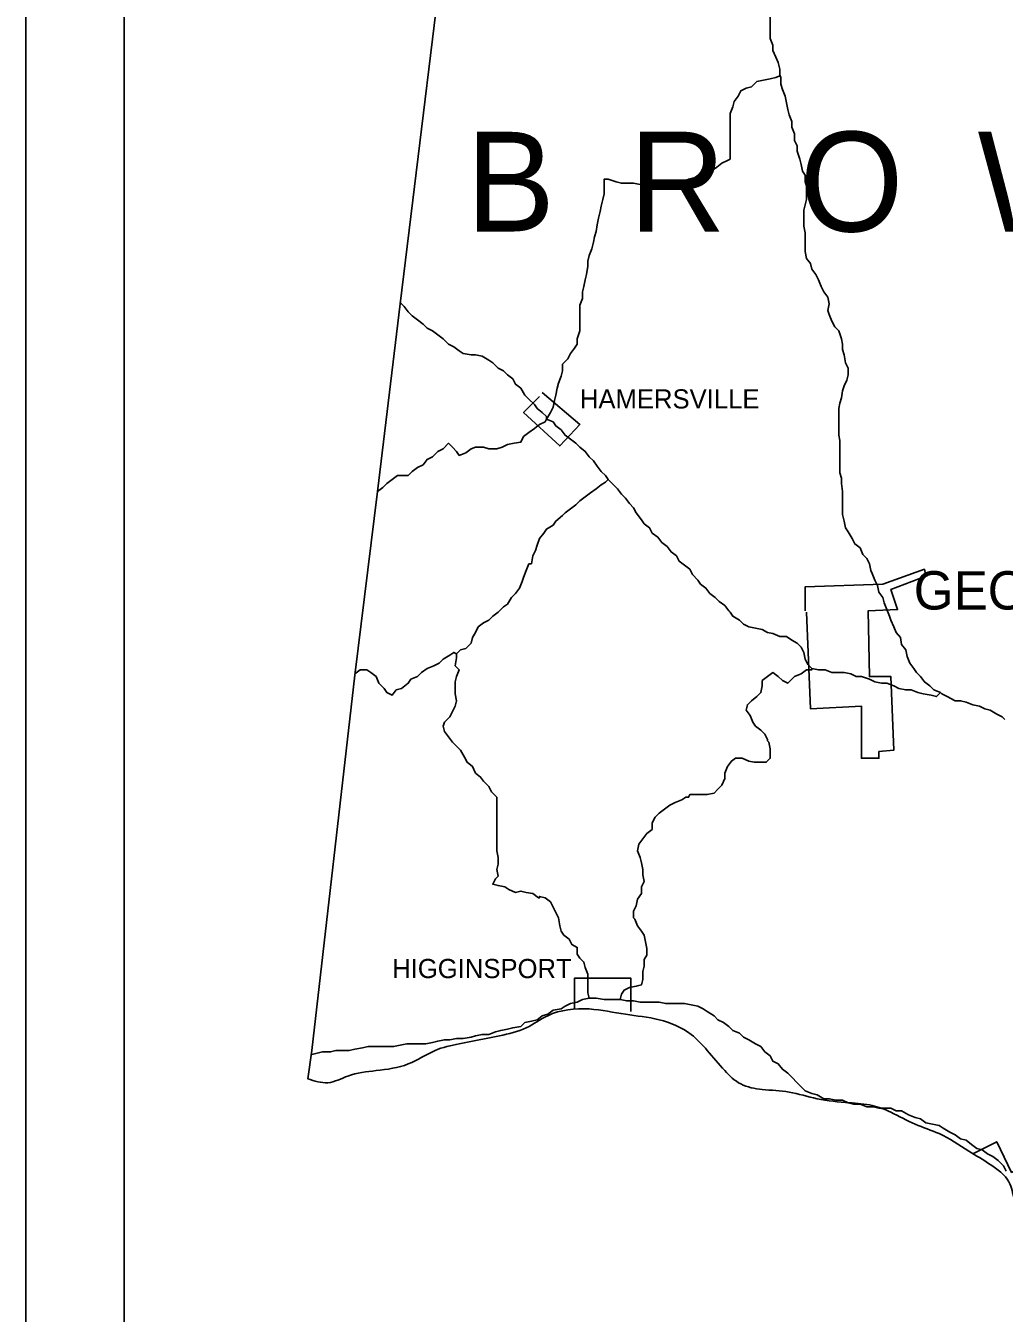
# Model space of a CAD drawing. Extents: x 0 to 40.2, y 0 to 22.
# Drawn here: x 2 to 2.995, y 16.376 to 17.685 of the extents above; entities that cross this region are included whole.
import ezdxf

# ---------------------------------------------------------------- set-up
doc = ezdxf.new("R2010")
doc.units = 0
for name, color, linetype in [('Default', 7, 'Continuous'), ('SH_Data', 7, 'Continuous'), ('TR_Turning_Path1', 7, 'Continuous')]:
    doc.layers.add(name, color=color, linetype=linetype)

msp = doc.modelspace()

# ---------------------------------------------------------------- linework, layer by layer
at = {"layer": 'Default'}
for points in [[(2.5335, 18.7973), (2.5253, 18.6677), (2.5172, 18.545), (2.5049, 18.4291), (2.4899, 18.3105), (2.4872, 18.2764), (2.4708, 18.1374), (2.4531, 17.9969), (2.4354, 17.8497), (2.3808, 17.4025), (2.3576, 17.2116), (2.3345, 17.0248), (2.2908, 16.6431), (2.2867, 16.6144)], [(2.7667, 17.6356), (2.7667, 17.6411), (2.7653, 17.6479), (2.7626, 17.6533), (2.7598, 17.6602), (2.7598, 17.6656), (2.7571, 17.6724), (2.7571, 17.6792), (2.7571, 17.6861), (2.7571, 17.6929), (2.7571, 17.6983), (2.7585, 17.7052), (2.7598, 17.7106), (2.7598, 17.7174), (2.7598, 17.7256), (2.7598, 17.7311), (2.7598, 17.7379), (2.7653, 17.7433), (2.768, 17.7488), (2.7721, 17.7542), (2.7748, 17.7597), (2.7762, 17.7665), (2.7762, 17.7665)], [(2.7162, 17.5511), (2.7162, 17.5579), (2.7162, 17.5634), (2.7162, 17.5702), (2.7162, 17.577), (2.7162, 17.5824), (2.7162, 17.5893), (2.7162, 17.5961), (2.7189, 17.6029), (2.7203, 17.6084), (2.7244, 17.6138), (2.7271, 17.6193), (2.7326, 17.622), (2.738, 17.6233), (2.7435, 17.6288), (2.7503, 17.6302), (2.7571, 17.6315), (2.7626, 17.6329), (2.7667, 17.6343), (2.7667, 17.6356)], [(2.7898, 17.5375), (2.7885, 17.5443), (2.7871, 17.5497), (2.7844, 17.5579), (2.7844, 17.5634), (2.7817, 17.5688), (2.7817, 17.5756), (2.7789, 17.5824), (2.7789, 17.5879), (2.7762, 17.5947), (2.7748, 17.6002), (2.7735, 17.607), (2.7721, 17.6138), (2.7694, 17.6206), (2.768, 17.6261), (2.768, 17.6329), (2.7667, 17.6356)], [(2.5799, 17.4761), (2.5812, 17.4829), (2.5826, 17.4897), (2.584, 17.4966), (2.5853, 17.502), (2.5867, 17.5088), (2.5881, 17.5143), (2.5881, 17.5211), (2.5881, 17.5293), (2.5921, 17.5293), (2.6003, 17.5265), (2.6058, 17.5252), (2.6112, 17.5252), (2.6181, 17.5252), (2.6249, 17.5238), (2.6317, 17.5225), (2.6371, 17.5225), (2.644, 17.5225), (2.6508, 17.5211), (2.6562, 17.5197), (2.6617, 17.5225), (2.6685, 17.5252), (2.674, 17.5293), (2.6794, 17.5306), (2.6862, 17.532), (2.6917, 17.5334), (2.6971, 17.5375), (2.7026, 17.5415), (2.708, 17.5456), (2.7135, 17.5484), (2.7162, 17.5497), (2.7162, 17.5511)], [(2.7912, 17.4843), (2.7912, 17.4897), (2.7912, 17.4979), (2.7926, 17.5034), (2.7939, 17.5088), (2.7939, 17.5143), (2.7939, 17.5225), (2.7926, 17.5265), (2.7926, 17.5334), (2.7898, 17.5375)], [(2.8362, 17.3316), (2.8362, 17.337), (2.8335, 17.3425), (2.8321, 17.3507), (2.8307, 17.3561), (2.8307, 17.3616), (2.8294, 17.367), (2.8267, 17.3752), (2.8226, 17.3793), (2.8198, 17.3848), (2.8171, 17.3916), (2.8157, 17.3957), (2.8171, 17.4025), (2.8157, 17.4093), (2.8117, 17.4147), (2.8089, 17.4202), (2.8062, 17.427), (2.8035, 17.4325), (2.7994, 17.4379), (2.798, 17.4434), (2.7939, 17.4488), (2.7926, 17.4556), (2.7926, 17.4625), (2.7926, 17.4679), (2.7926, 17.4747), (2.7912, 17.4816), (2.7912, 17.4843), (2.7912, 17.4843)], [(2.5294, 17.2852), (2.5335, 17.292), (2.5362, 17.2975), (2.5376, 17.3043), (2.539, 17.3098), (2.5403, 17.3166), (2.5417, 17.322), (2.5444, 17.3289), (2.5458, 17.3343), (2.5458, 17.3411), (2.5512, 17.3466), (2.554, 17.352), (2.5581, 17.3575), (2.5608, 17.3616), (2.5608, 17.367), (2.5635, 17.3752), (2.5635, 17.382), (2.5635, 17.3875), (2.5635, 17.3943), (2.5635, 17.4011), (2.5662, 17.4079), (2.5662, 17.4147), (2.5676, 17.4202), (2.569, 17.427), (2.5703, 17.4325), (2.5717, 17.4407), (2.5717, 17.4461), (2.5731, 17.4516), (2.5758, 17.4584), (2.5772, 17.4652), (2.5785, 17.4706), (2.5799, 17.4761), (2.5799, 17.4761)], [(2.3808, 17.4038), (2.3849, 17.3997), (2.389, 17.3943), (2.3931, 17.3902), (2.3985, 17.3861), (2.404, 17.382), (2.4081, 17.3779), (2.4135, 17.3752), (2.419, 17.3711), (2.4244, 17.367), (2.4299, 17.3616), (2.4354, 17.3588), (2.4408, 17.3548), (2.4449, 17.352), (2.4531, 17.3507), (2.4572, 17.3507), (2.464, 17.3493), (2.4708, 17.3452), (2.4749, 17.3425), (2.4803, 17.337), (2.4858, 17.3343), (2.4899, 17.3302), (2.4953, 17.3261), (2.4981, 17.3207), (2.5035, 17.3166), (2.5076, 17.3098), (2.5117, 17.3057), (2.5172, 17.3002), (2.5199, 17.2961), (2.5253, 17.292), (2.5294, 17.2879), (2.5294, 17.2852)], [(2.3808, 17.4038), (2.3849, 17.3997), (2.389, 17.3943), (2.3931, 17.3902), (2.3985, 17.3861), (2.404, 17.382), (2.4081, 17.3779), (2.4135, 17.3752), (2.419, 17.3711), (2.4244, 17.367), (2.4299, 17.3616), (2.4354, 17.3588), (2.4408, 17.3548), (2.4449, 17.352), (2.4531, 17.3507), (2.4572, 17.3507), (2.464, 17.3493), (2.4708, 17.3452), (2.4749, 17.3425), (2.4803, 17.337), (2.4858, 17.3343), (2.4899, 17.3302), (2.4953, 17.3261), (2.4981, 17.3207), (2.5035, 17.3166), (2.5076, 17.3098), (2.5117, 17.3057), (2.5172, 17.3002), (2.5199, 17.2961), (2.5253, 17.292), (2.5294, 17.2879), (2.5294, 17.2852)], [(2.828, 17.2498), (2.828, 17.2552), (2.828, 17.2634), (2.8267, 17.2689), (2.8267, 17.2757), (2.8267, 17.2825), (2.8267, 17.2879), (2.8267, 17.2961), (2.828, 17.3016), (2.8294, 17.307), (2.8307, 17.3139), (2.8321, 17.3193), (2.8348, 17.3248), (2.8362, 17.3302), (2.8362, 17.3316)], [(2.5226, 17.3084), (2.5063, 17.292), (2.5431, 17.258), (2.5635, 17.2798), (2.5253, 17.3125)], [(2.4408, 17.2484), (2.4476, 17.2511), (2.4531, 17.2552), (2.4572, 17.2566), (2.4654, 17.2566), (2.4708, 17.2552), (2.479, 17.2552), (2.4844, 17.2566), (2.4899, 17.2593), (2.4967, 17.2607), (2.5035, 17.262), (2.5063, 17.2675), (2.5117, 17.2716), (2.5172, 17.2757), (2.5226, 17.2798), (2.5281, 17.2825), (2.5294, 17.2852), (2.5294, 17.2852)], [(2.5294, 17.2852), (2.5362, 17.2825), (2.539, 17.2784), (2.5444, 17.2743), (2.5485, 17.2689), (2.554, 17.2648), (2.5594, 17.2607), (2.5635, 17.2566), (2.569, 17.2525), (2.5731, 17.247), (2.5772, 17.243), (2.5812, 17.2375), (2.5853, 17.232), (2.5894, 17.228), (2.5921, 17.2239)], [(2.5294, 17.2852), (2.5362, 17.2825), (2.539, 17.2784), (2.5444, 17.2743), (2.5485, 17.2689), (2.554, 17.2648), (2.5594, 17.2607), (2.5635, 17.2566), (2.569, 17.2525), (2.5731, 17.247), (2.5772, 17.243), (2.5812, 17.2375), (2.5853, 17.232), (2.5894, 17.228), (2.5921, 17.2239)], [(2.3576, 17.2116), (2.3631, 17.2157), (2.3672, 17.2198), (2.3726, 17.2239), (2.3781, 17.228), (2.3835, 17.228), (2.389, 17.228), (2.3931, 17.232), (2.3985, 17.2361), (2.404, 17.2389), (2.4081, 17.2443), (2.4135, 17.247), (2.419, 17.2525), (2.4244, 17.2552), (2.4299, 17.2607), (2.434, 17.2566), (2.4381, 17.2525), (2.4408, 17.2484), (2.4408, 17.2484)], [(2.8307, 17.1993), (2.8307, 17.2061), (2.8307, 17.2116), (2.8294, 17.2198), (2.8294, 17.2252), (2.828, 17.2307), (2.828, 17.2375), (2.828, 17.2443), (2.828, 17.2498)], [(2.5144, 17.138), (2.5158, 17.1462), (2.5185, 17.1516), (2.5199, 17.1571), (2.5226, 17.1639), (2.5267, 17.1693), (2.5294, 17.1734), (2.5362, 17.1775), (2.539, 17.1816), (2.5458, 17.1871), (2.5485, 17.1898), (2.554, 17.1939), (2.5594, 17.198), (2.5635, 17.2021), (2.569, 17.2061), (2.5744, 17.2102), (2.5799, 17.2143), (2.5853, 17.2184), (2.5894, 17.2211), (2.5921, 17.2239)], [(2.5921, 17.2239), (2.5962, 17.2198), (2.6017, 17.2143), (2.6058, 17.2089), (2.6099, 17.2048), (2.614, 17.1993), (2.6181, 17.1952), (2.6208, 17.1898), (2.6262, 17.183), (2.629, 17.1789), (2.6344, 17.1748), (2.6371, 17.1693), (2.6426, 17.1652), (2.6467, 17.1598), (2.6521, 17.1557), (2.6562, 17.1502), (2.6617, 17.1462), (2.6644, 17.1407), (2.6699, 17.1366), (2.6753, 17.1325), (2.678, 17.1271), (2.6835, 17.1216), (2.6862, 17.1175), (2.6917, 17.1134), (2.6958, 17.108), (2.7012, 17.1039), (2.7053, 17.0998), (2.7108, 17.0957), (2.7149, 17.0903), (2.7162, 17.0889)], [(2.5921, 17.2239), (2.5962, 17.2198), (2.6017, 17.2143), (2.6058, 17.2089), (2.6099, 17.2048), (2.614, 17.1993), (2.6181, 17.1952), (2.6208, 17.1898), (2.6262, 17.183), (2.629, 17.1789), (2.6344, 17.1748), (2.6371, 17.1693), (2.6426, 17.1652), (2.6467, 17.1598), (2.6521, 17.1557), (2.6562, 17.1502), (2.6617, 17.1462), (2.6644, 17.1407), (2.6699, 17.1366), (2.6753, 17.1325), (2.678, 17.1271), (2.6835, 17.1216), (2.6862, 17.1175), (2.6917, 17.1134), (2.6958, 17.108), (2.7012, 17.1039), (2.7053, 17.0998), (2.7108, 17.0957), (2.7149, 17.0903), (2.7162, 17.0889)], [(2.8594, 17.1312), (2.858, 17.138), (2.8553, 17.1434), (2.8512, 17.1475), (2.8485, 17.1543), (2.843, 17.1584), (2.8403, 17.1639), (2.8362, 17.1707), (2.8335, 17.1748), (2.8321, 17.1816), (2.8307, 17.1884), (2.8307, 17.1939), (2.8307, 17.1993)], [(2.4381, 17.0466), (2.4422, 17.0507), (2.4476, 17.0521), (2.4531, 17.0575), (2.4544, 17.063), (2.4572, 17.0684), (2.4599, 17.0739), (2.4654, 17.078), (2.4708, 17.0807), (2.4749, 17.0848), (2.4803, 17.0889), (2.4858, 17.0943), (2.4899, 17.0971), (2.494, 17.1039), (2.4981, 17.108), (2.5022, 17.1134), (2.5049, 17.1202), (2.5063, 17.1243), (2.509, 17.1312), (2.5117, 17.138), (2.5144, 17.138)], [(2.7939, 17.0889), (2.798, 16.9907), (2.8498, 16.9934), (2.8498, 16.9403), (2.8676, 16.9403), (2.8676, 16.9471), (2.8826, 16.9485), (2.8798, 17.0234), (2.858, 17.0234), (2.8567, 17.0903), (2.8866, 17.0916), (2.8798, 17.1121), (2.9153, 17.1257), (2.9139, 17.1325), (2.8717, 17.1175), (2.7926, 17.1148), (2.7926, 17.0903)], [(2.9303, 17.0071), (2.9235, 17.0098), (2.9194, 17.0139), (2.9139, 17.018), (2.9098, 17.0234), (2.9057, 17.0275), (2.903, 17.0316), (2.8989, 17.0371), (2.8962, 17.0439), (2.8948, 17.0507), (2.8907, 17.0562), (2.8894, 17.063), (2.8853, 17.0684), (2.8826, 17.0739), (2.8798, 17.0807), (2.8785, 17.0848), (2.8757, 17.0916), (2.873, 17.0984), (2.8717, 17.1039), (2.8676, 17.1093), (2.8662, 17.1162), (2.8635, 17.1216), (2.8607, 17.1284), (2.8594, 17.1312)], [(2.7162, 17.0889), (2.7189, 17.0848), (2.7258, 17.0807), (2.7299, 17.0766), (2.7353, 17.0739), (2.7421, 17.0725), (2.7489, 17.0712), (2.7544, 17.0684), (2.7598, 17.0671), (2.7667, 17.0643), (2.7735, 17.0643), (2.7789, 17.0603), (2.7844, 17.0575), (2.7885, 17.0534), (2.7912, 17.048), (2.7926, 17.0412), (2.7953, 17.0357), (2.7994, 17.0316), (2.7994, 17.0316)], [(2.7162, 17.0889), (2.7189, 17.0848), (2.7258, 17.0807), (2.7299, 17.0766), (2.7353, 17.0739), (2.7421, 17.0725), (2.7489, 17.0712), (2.7544, 17.0684), (2.7598, 17.0671), (2.7667, 17.0643), (2.7735, 17.0643), (2.7789, 17.0603), (2.7844, 17.0575), (2.7885, 17.0534), (2.7912, 17.048), (2.7926, 17.0412), (2.7953, 17.0357), (2.7994, 17.0316), (2.7994, 17.0316)], [(2.3345, 17.0262), (2.3399, 17.0303), (2.3467, 17.0303), (2.3508, 17.0275), (2.3563, 17.0234), (2.359, 17.0166), (2.3645, 17.0112), (2.3672, 17.0071), (2.3726, 17.0044), (2.3767, 17.0098), (2.3822, 17.0112), (2.389, 17.0166), (2.3917, 17.0207), (2.3985, 17.0234), (2.4026, 17.0275), (2.4081, 17.0316), (2.4149, 17.0344), (2.4204, 17.0371), (2.4244, 17.0412), (2.4313, 17.0453), (2.4354, 17.048), (2.4381, 17.0466)], [(2.479, 16.9007), (2.4735, 16.9062), (2.4708, 16.9116), (2.4654, 16.9171), (2.4626, 16.9212), (2.4572, 16.9253), (2.4544, 16.9321), (2.449, 16.9362), (2.4463, 16.9416), (2.4422, 16.9485), (2.4381, 16.9525), (2.434, 16.9566), (2.4299, 16.9621), (2.4258, 16.9675), (2.4244, 16.973), (2.4258, 16.9771), (2.4313, 16.9825), (2.434, 16.988), (2.4367, 16.9934), (2.4381, 16.9989), (2.4367, 17.0057), (2.4367, 17.0112), (2.4367, 17.018), (2.4381, 17.0234), (2.4408, 17.0303), (2.4367, 17.0344), (2.4381, 17.0425), (2.4381, 17.0439), (2.4381, 17.0466)], [(2.7544, 16.9594), (2.7517, 16.9648), (2.7476, 16.9689), (2.7421, 16.973), (2.7394, 16.9771), (2.7367, 16.9839), (2.7326, 16.9894), (2.7339, 16.9948), (2.738, 16.9989), (2.7435, 17.003), (2.7476, 17.0071), (2.7489, 17.0139), (2.7489, 17.0194), (2.7544, 17.0234), (2.7598, 17.0275), (2.7653, 17.0234), (2.7694, 17.0194), (2.7748, 17.0166), (2.7789, 17.0207), (2.7817, 17.0234), (2.7885, 17.0262), (2.7939, 17.0303), (2.7994, 17.0303), (2.7994, 17.0316)], [(2.7994, 17.0316), (2.8062, 17.0303), (2.813, 17.0303), (2.8198, 17.0275), (2.8253, 17.0275), (2.8321, 17.0275), (2.8389, 17.0262), (2.8444, 17.0234), (2.8498, 17.0234), (2.858, 17.0207), (2.8635, 17.018), (2.8703, 17.0166), (2.8757, 17.0166), (2.8826, 17.0139), (2.888, 17.0112), (2.8948, 17.0098), (2.9003, 17.0098), (2.9071, 17.0071), (2.9126, 17.0057), (2.9207, 17.0044), (2.9262, 17.003), (2.9289, 17.0057), (2.9303, 17.0071)], [(2.7994, 17.0316), (2.8062, 17.0303), (2.813, 17.0303), (2.8198, 17.0275), (2.8253, 17.0275), (2.8321, 17.0275), (2.8389, 17.0262), (2.8444, 17.0234), (2.8498, 17.0234), (2.858, 17.0207), (2.8635, 17.018), (2.8703, 17.0166), (2.8757, 17.0166), (2.8826, 17.0139), (2.888, 17.0112), (2.8948, 17.0098), (2.9003, 17.0098), (2.9071, 17.0071), (2.9126, 17.0057), (2.9207, 17.0044), (2.9262, 17.003), (2.9289, 17.0057), (2.9303, 17.0071)], [(2.9303, 17.0071), (2.9316, 17.0057), (2.9371, 17.003), (2.9453, 16.9989), (2.9507, 16.9989), (2.9562, 16.9975), (2.963, 16.9948), (2.9698, 16.9934), (2.9753, 16.9907), (2.9807, 16.9894), (2.9875, 16.9853), (2.993, 16.9825)], [(2.9303, 17.0071), (2.9316, 17.0057), (2.9371, 17.003), (2.9453, 16.9989), (2.9507, 16.9989), (2.9562, 16.9975), (2.963, 16.9948), (2.9698, 16.9934), (2.9753, 16.9907), (2.9807, 16.9894), (2.9875, 16.9853), (2.993, 16.9825)], [(2.993, 16.9825), (2.9875, 16.9853), (2.9807, 16.9894), (2.9753, 16.9907), (2.9698, 16.9934), (2.963, 16.9948), (2.9562, 16.9975), (2.9507, 16.9989), (2.9453, 16.9989), (2.9371, 17.003), (2.9316, 17.0057), (2.9303, 17.0071)], [(2.9957, 16.9798), (2.9944, 16.9812), (2.993, 16.9825)], [(2.6753, 16.9035), (2.6808, 16.9035), (2.6862, 16.9035), (2.693, 16.9035), (2.6999, 16.9048), (2.7039, 16.9089), (2.708, 16.913), (2.7108, 16.9198), (2.7108, 16.9253), (2.7135, 16.9321), (2.7176, 16.9375), (2.7217, 16.9403), (2.7285, 16.9403), (2.7353, 16.9375), (2.7408, 16.9362), (2.7476, 16.9362), (2.753, 16.9362), (2.7571, 16.9403), (2.7571, 16.9444), (2.7571, 16.9498), (2.7558, 16.9566), (2.7544, 16.958), (2.7544, 16.9594)], [(2.5213, 16.7985), (2.5158, 16.8026), (2.509, 16.8039), (2.5035, 16.8053), (2.4981, 16.8039), (2.4913, 16.8067), (2.4872, 16.8094), (2.4803, 16.8108), (2.4749, 16.8121), (2.4776, 16.8176), (2.4803, 16.8203), (2.479, 16.8271), (2.4803, 16.8326), (2.4803, 16.8394), (2.479, 16.8462), (2.479, 16.8517), (2.479, 16.8598), (2.479, 16.8639), (2.479, 16.8707), (2.479, 16.8789), (2.479, 16.8844), (2.479, 16.8926), (2.479, 16.8994), (2.479, 16.8994), (2.479, 16.9007)], [(2.6181, 16.778), (2.6181, 16.7848), (2.6208, 16.7903), (2.6221, 16.7971), (2.6262, 16.8026), (2.6262, 16.8094), (2.629, 16.8148), (2.6276, 16.8217), (2.6276, 16.8271), (2.6262, 16.8339), (2.6249, 16.8394), (2.6221, 16.8462), (2.6235, 16.853), (2.6276, 16.8585), (2.6317, 16.8639), (2.6371, 16.868), (2.6371, 16.8748), (2.6399, 16.8803), (2.644, 16.8844), (2.6494, 16.8885), (2.6549, 16.8926), (2.6603, 16.8953), (2.6671, 16.898), (2.6712, 16.9007), (2.674, 16.9007), (2.6753, 16.9035)], [(2.5731, 16.6962), (2.5717, 16.7017), (2.5717, 16.7085), (2.5717, 16.7153), (2.5717, 16.7208), (2.569, 16.7276), (2.5676, 16.733), (2.5635, 16.7371), (2.5608, 16.7412), (2.5608, 16.748), (2.5553, 16.7508), (2.5526, 16.7562), (2.5472, 16.7603), (2.5444, 16.7644), (2.5431, 16.7698), (2.5417, 16.778), (2.539, 16.7835), (2.5362, 16.7889), (2.5335, 16.7944), (2.5281, 16.7985), (2.5226, 16.7998), (2.5226, 16.7985), (2.5213, 16.7985)], [(2.6044, 16.6949), (2.6058, 16.7003), (2.6085, 16.7044), (2.614, 16.7071), (2.6208, 16.7085), (2.6262, 16.7099), (2.6276, 16.7153), (2.6276, 16.7235), (2.629, 16.7289), (2.629, 16.7358), (2.6317, 16.7399), (2.6317, 16.7467), (2.6303, 16.7535), (2.629, 16.7603), (2.6262, 16.7644), (2.6221, 16.7698), (2.6194, 16.7767), (2.6181, 16.778)], [(2.6153, 16.6826), (2.6153, 16.7167), (2.5581, 16.7167), (2.5581, 16.6853)], [(2.2908, 16.639), (2.2963, 16.6403), (2.3017, 16.6417), (2.3099, 16.6417), (2.3154, 16.6431), (2.3236, 16.6431), (2.329, 16.6431), (2.3345, 16.6444), (2.3426, 16.6458), (2.3481, 16.6471), (2.3563, 16.6471), (2.3617, 16.6471), (2.3672, 16.6471), (2.374, 16.6471), (2.3808, 16.6485), (2.3876, 16.6499), (2.3931, 16.6499), (2.3999, 16.6499), (2.4067, 16.6499), (2.4135, 16.6512), (2.419, 16.6526), (2.4258, 16.654), (2.4313, 16.654), (2.4381, 16.6553), (2.4449, 16.6553), (2.4531, 16.6567), (2.4572, 16.658), (2.464, 16.6594), (2.4708, 16.6594), (2.4776, 16.6621), (2.4831, 16.6635), (2.4899, 16.6649), (2.4953, 16.6662), (2.5035, 16.6676), (2.5076, 16.6717), (2.5144, 16.673), (2.5199, 16.6744), (2.5253, 16.6785), (2.5308, 16.6799), (2.5362, 16.684), (2.5444, 16.6853), (2.5485, 16.688), (2.554, 16.6908), (2.5608, 16.6921), (2.5662, 16.6949), (2.5731, 16.6962), (2.5731, 16.6962)], [(2.5731, 16.6962), (2.5799, 16.6962), (2.5881, 16.6949), (2.5949, 16.6949), (2.6003, 16.6949), (2.6044, 16.6949)], [(2.6044, 16.6949), (2.6112, 16.6935), (2.6181, 16.6935), (2.6249, 16.6921), (2.6317, 16.6921), (2.6371, 16.6921), (2.644, 16.6921), (2.6508, 16.6908), (2.6562, 16.6908), (2.663, 16.6908), (2.6699, 16.6908), (2.6767, 16.6894), (2.6835, 16.688), (2.689, 16.6853), (2.693, 16.6826), (2.6999, 16.6785), (2.7039, 16.6744), (2.7094, 16.6717), (2.7149, 16.6676), (2.7189, 16.6635), (2.7258, 16.6608), (2.7258, 16.6608)], [(2.7258, 16.6608), (2.7299, 16.6567), (2.7353, 16.654), (2.7421, 16.6499), (2.7476, 16.6471), (2.7517, 16.6417), (2.7571, 16.6376), (2.7598, 16.6321), (2.7653, 16.6294), (2.7694, 16.624), (2.7748, 16.6199), (2.7789, 16.6158), (2.7844, 16.6103), (2.7885, 16.6062), (2.7926, 16.6021), (2.7994, 16.5994), (2.8048, 16.5981), (2.8117, 16.594), (2.8171, 16.594), (2.8239, 16.5926), (2.8307, 16.5926), (2.8362, 16.5899), (2.8417, 16.5885), (2.8485, 16.5885), (2.8553, 16.5858), (2.8621, 16.5858), (2.8676, 16.5844), (2.8744, 16.5844), (2.8798, 16.5844), (2.8853, 16.5817)], [(2.8853, 16.5817), (2.8907, 16.5817), (2.8976, 16.5776), (2.9044, 16.5749), (2.9098, 16.5735), (2.9153, 16.5694), (2.9221, 16.5681), (2.9289, 16.5667), (2.933, 16.564), (2.9398, 16.5599), (2.9453, 16.5572), (2.9507, 16.5531), (2.9562, 16.5517), (2.9616, 16.5476), (2.9671, 16.5435), (2.9725, 16.5422), (2.978, 16.5381), (2.9835, 16.5353), (2.9889, 16.5312), (2.9944, 16.5258), (2.9971, 16.5203)], [(3.0325, 16.3881), (3.0871, 16.4154), (3.0434, 16.5067), (3.0707, 16.519), (3.0598, 16.5476), (3.0025, 16.519), (2.9875, 16.5503), (2.963, 16.5381)]]:
    msp.add_lwpolyline(points, dxfattribs=at)
msp.add_spline([(3.5097, 16.0009), (3.4893, 16.0009), (3.4825, 16.0091), (3.4688, 16.0118), (3.4634, 16.0213), (3.4552, 16.0281), (3.4416, 16.0281), (3.4197, 16.0363), (3.3979, 16.0336), (3.3652, 16.0404), (3.3366, 16.05), (3.3093, 16.0541), (3.2929, 16.0609), (3.2793, 16.0704), (3.2725, 16.0827), (3.2589, 16.1059), (3.2575, 16.1318), (3.2534, 16.159), (3.2466, 16.1809), (3.2439, 16.2122), (3.237, 16.2463), (3.2261, 16.2667), (3.2098, 16.2817), (3.1907, 16.2954), (3.1743, 16.3022), (3.1498, 16.3104), (3.1198, 16.3131), (3.0966, 16.3213), (3.083, 16.3308), (3.0639, 16.3445), (3.0475, 16.3554), (3.0339, 16.3717), (3.0271, 16.3935), (3.0271, 16.414), (3.0203, 16.4344), (3.0134, 16.4685), (3.0053, 16.4917), (2.9998, 16.5094), (2.9807, 16.5272), (2.9589, 16.5408), (2.9289, 16.5585), (2.9044, 16.5681), (2.8798, 16.5803), (2.8607, 16.5871), (2.8376, 16.5899), (2.8048, 16.594), (2.7762, 16.6008), (2.7489, 16.6035), (2.7271, 16.609), (2.7108, 16.6226), (2.693, 16.6431), (2.6767, 16.6594), (2.644, 16.6744), (2.6099, 16.6799), (2.5731, 16.6853), (2.5308, 16.6785), (2.509, 16.6662), (2.4817, 16.658), (2.4408, 16.6499), (2.4163, 16.6431), (2.389, 16.6294), (2.3563, 16.6226), (2.3276, 16.6171), (2.3072, 16.6103), (2.2867, 16.6144)], degree=3, dxfattribs=at)
at = {"layer": 'SH_Data'}
for p, q in [((2, 21), (2, 14)), ((2.1, 20.9), (2.1, 14.1))]:
    msp.add_line(p, q, dxfattribs=at)

# ---------------------------------------------------------------- texts
at = {"layer": 'Default'}
for s, height, p in [('HAMERSVILLE', 0.019502, (2.5635, 17.2961)), ('GEORGETOWN', 0.039, (2.903, 17.0916)), ('HIGGINSPORT', 0.019502, (2.3726, 16.7167))]:
    msp.add_text(s, height=height, dxfattribs=at).set_placement(p)
at = {"layer": 'TR_Turning_Path1'}
msp.add_text('B  R  O  W  N', height=0.101489, dxfattribs=at).set_placement((2.4476, 17.4761))

doc.saveas('drawing.dxf')
